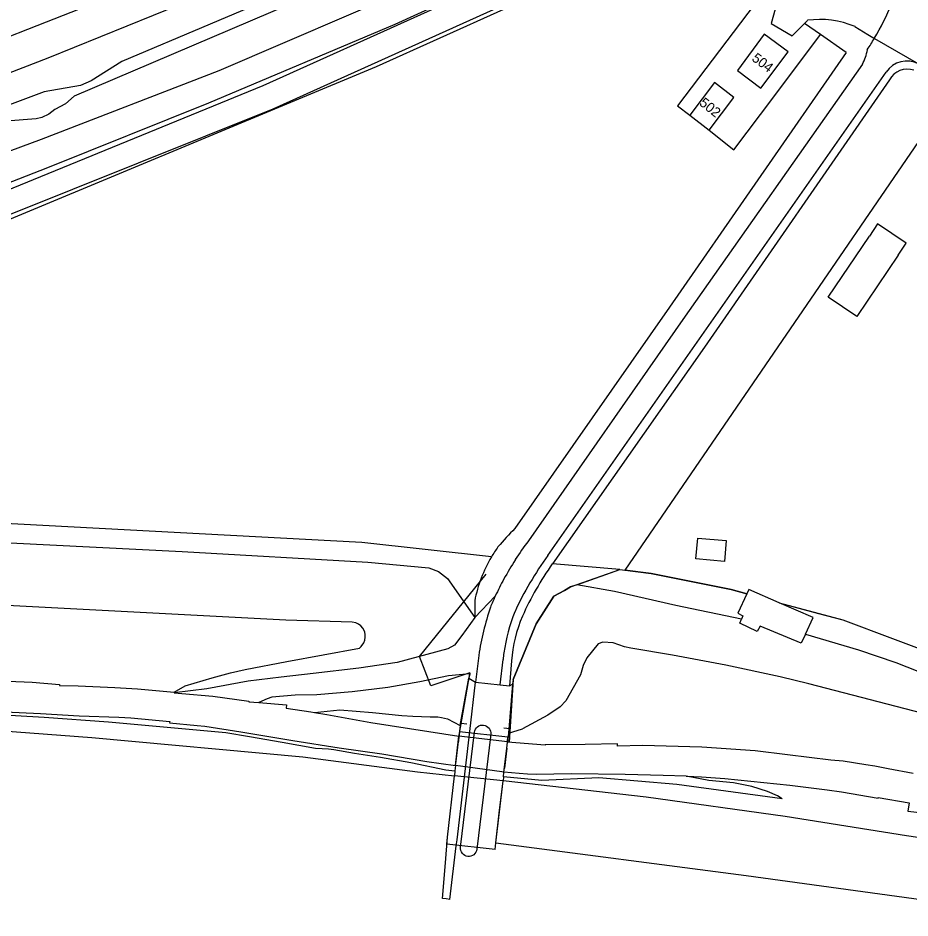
# Model space of a CAD drawing. Extents: x 194485 to 197793, y 468269 to 470822.
# Drawn here: x 195940.6 to 196049.6, y 469112.8 to 469222.9 of the extents above; entities that cross this region are included whole.
import ezdxf

# ---------------------------------------------------------------- set-up
doc = ezdxf.new("R2010")
doc.units = 0
for name, color, linetype in [('BGT begrenzing kruinlijn', 7, 'Continuous'), ('BGT grensvlak begroeid terreindeel', 7, 'Continuous'), ('BGT grensvlak begroeid terreindeel LR', 7, 'Continuous'), ('BGT grensvlak onbegroeid terreindeel', 7, 'Continuous'), ('BGT grensvlak onbegroeid terreindeel plus 1', 7, 'Continuous'), ('BGT grensvlak overbruggingsdeel plus 1', 7, 'Continuous'), ('BGT grensvlak overig bouwwerk uitbreiding populatie', 7, 'Continuous'), ('BGT grensvlak pand op maaiveld', 7, 'Continuous'), ('BGT grensvlak tunneldeel min 1', 7, 'Continuous'), ('BGT grensvlak vegetatieobject', 7, 'Continuous'), ('BGT grensvlak waterdeel', 7, 'Continuous'), ('BGT grensvlak wegdeel', 7, 'Continuous'), ('BGT grensvlak wegdeel plus 1', 7, 'Continuous'), ('BGT lijnelement scheiding hek', 7, 'Continuous'), ('BGT lijnelement spoor trein', 7, 'Continuous'), ('BGT tekst huisnummerreeks', 7, 'Continuous')]:
    doc.layers.add(name, color=color, linetype=linetype)

msp = doc.modelspace()

# ---------------------------------------------------------------- linework, layer by layer
at = {"layer": 'BGT begrenzing kruinlijn'}
for p, q in [((196011.53, 469146.34), (196010.15, 469144.64)), ((196012.1, 469146.57), (196011.53, 469146.34)), ((196013.35, 469146.47), (196012.1, 469146.57)), ((196014.75, 469146), (196013.35, 469146.47)), ((196015.5, 469145.83), (196014.75, 469146)), ((196020.61, 469144.98), (196015.5, 469145.83)), ((196027.15, 469143.77), (196020.61, 469144.98)), ((196009.7, 469143.73), (196009.37, 469142.57)), ((196010.15, 469144.64), (196009.7, 469143.73)), ((196033.79, 469142.31), (196027.15, 469143.77)), ((196009.37, 469142.57), (196007.59, 469139.39)), ((196037.29, 469141.47), (196033.79, 469142.31)), ((196058.8, 469135.89), (196037.29, 469141.47)), ((196007.59, 469139.39), (196006.86, 469138.67)), ((196006.86, 469138.67), (196005.36, 469137.62)), ((196005.36, 469137.62), (196002.27, 469135.98)), ((196000.55, 469135.45), (196002.27, 469135.98))]:
    msp.add_line(p, q, dxfattribs=at)
for points in [[(196011.68, 469240.59), (196004.13, 469237.75), (195988.29, 469230.77), (195947.48, 469213.34), (195946.39, 469212.38), (195945.1, 469211.7), (195944.35, 469211.14), (195943.52, 469210.73), (195942.81, 469210.57), (195939.16, 469210.28), (195897.28, 469195.19), (195879.53, 469189.73), (195853.15, 469181.35), (195844.04, 469178.68), (195834.06, 469175.98)], [(195959.71, 469140.46), (195961.05, 469141.23), (195964.32, 469142.2), (195966.59, 469142.81), (195968.36, 469143.22), (195973.47, 469144.19), (195982.36, 469145.84), (195982.57, 469146.05), (195982.88, 469146.48), (195982.98, 469146.79), (195983.03, 469147.17), (195983.03, 469147.5), (195982.99, 469147.79), (195982.91, 469148.01), (195982.74, 469148.29), (195982.53, 469148.55), (195982.21, 469148.78), (195981.88, 469148.92), (195981.46, 469149), (195973.34, 469149.24), (195926.85, 469151.69), (195915.86, 469151.77)], [(195894.77, 469139.74), (195905.45, 469139.19), (195917.79, 469138.9), (195943.78, 469137.41), (195951.68, 469136.83), (195966.02, 469135.53), (195968.88, 469135.04), (195972.89, 469134.34), (195976.98, 469133.62), (195977.78, 469133.57), (195978.57, 469133.52), (195979.19, 469133.45), (195981.72, 469133.01), (195984.91, 469132.49), (195988.63, 469131.83), (195992.9, 469130.96), (195994.02, 469130.82)], [(195976.85, 469137.97), (195979.96, 469138.28), (195983.94, 469137.98), (195987.53, 469137.61), (195988.86, 469137.5), (195990.98, 469137.44), (195991.91, 469137.43), (195992.36, 469137.37), (195993.1, 469137.17), (195994.66, 469136.39)], [(196034, 469127.39), (196021.12, 469129.16), (196011.62, 469129.99), (196004.65, 469129.64), (195999.94, 469130.08)]]:
    msp.add_lwpolyline(points, dxfattribs=at)
at = {"layer": 'BGT grensvlak begroeid terreindeel'}
for p, q in [((196041.85, 469218.68), (196038.72, 469220.86)), ((196014.18, 469155.45), (196005.92, 469156.14)), ((196008.91, 469153.58), (196014.18, 469155.45)), ((196014.18, 469155.45), (196014.79, 469155.37)), ((195996.43, 469151.62), (195996.45, 469149.56))]:
    msp.add_line(p, q, dxfattribs=at)
for points in [[(195835.93, 469168.56), (195850.59, 469172.63), (195876.12, 469179.94), (195889.94, 469184.48), (195902.05, 469188.58), (195907.49, 469190.51), (195924.09, 469196.72), (195944.24, 469204.6), (195963.93, 469212.5), (195986.7, 469222.13), (196011.58, 469233.49), (196012.58, 469233.54), (196013.02, 469233.37), (196013.69, 469232.61), (196014.11, 469231.67), (196014.15, 469230.9), (196013.89, 469230.29)], [(195856.53, 469168.61), (195883.77, 469178.59), (195931.54, 469194.93), (195984.41, 469216.96), (196000, 469223.96), (196013.89, 469230.29)], [(196041.85, 469218.68), (196020.23, 469187.52), (196001.35, 469160.46)], [(195998.47, 469156.98), (195982.63, 469158.77), (195934.41, 469161.31), (195856.66, 469163.48), (195856.53, 469168.61)], [(195890.63, 469158.09), (195890.8, 469160.9), (195893.82, 469161.05), (195903.99, 469160.77), (195917.76, 469160.03), (195939.63, 469158.73), (195960.68, 469157.64), (195983.36, 469156.35), (195990.82, 469155.67), (195992.01, 469155.2), (195993.11, 469154.34), (195996.45, 469149.56)], [(196008.91, 469153.58), (196008.16, 469153.31), (196007.41, 469152.89), (196006.11, 469152.17), (196003.95, 469148.82), (196001.12, 469141.99), (196001.07, 469141.41)], [(196034, 469127.39), (196033.46, 469127.76), (196032.23, 469128.29), (196030.3, 469128.9), (196028.08, 469129.35), (196025.07, 469129.64), (196022.3, 469130.16)]]:
    msp.add_lwpolyline(points, dxfattribs=at)
for centre, radius, start, end in [((196031.27, 469130.89), 42.07, 135.3274, 139.5072), ((196012.97, 469148.31), 16.9, 144.1568, 149.1153), ((196012.7, 469148.48), 16.57, 149.1356, 169.0648)]:
    msp.add_arc(centre, radius, start, end, dxfattribs=at)
at = {"layer": 'BGT grensvlak begroeid terreindeel LR'}
for points in [[(196013.73, 469236.46), (196009.36, 469235.71), (195989.09, 469226.73), (195965.14, 469216.44), (195943.43, 469208.05), (195918.92, 469198.93), (195901.71, 469192.67), (195890.52, 469188.95), (195875.82, 469184.28), (195841.86, 469174.28), (195834.98, 469172.34)], [(196029.05, 469149.37), (196021.02, 469151.05), (196013.5, 469152.76), (196008.91, 469153.58)], [(196036.85, 469147.53), (196043.36, 469145.61), (196047.9, 469144.08), (196053.3, 469141.96), (196057.4, 469140.11), (196057.99, 469140.01), (196058.36, 469140.14), (196060.06, 469142.05)]]:
    msp.add_lwpolyline(points, dxfattribs=at)
at = {"layer": 'BGT grensvlak onbegroeid terreindeel'}
for p, q in [((196038.72, 469220.86), (196036.74, 469222.23)), ((196032.99, 469213.25), (196038.72, 469220.86)), ((196054.69, 469213.65), (196014.79, 469155.37)), ((195994.66, 469136.39), (195995.72, 469142.17)), ((195959.71, 469140.46), (195959.7, 469140.35)), ((195994.66, 469136.39), (195994.51, 469135.06)), ((195994.51, 469135.06), (195994.43, 469134.41)), ((195994.16, 469132.01), (195994.43, 469134.41)), ((195994.1, 469131.48), (195994.16, 469132.01)), ((195992.88, 469119.59), (195993.1, 469122.71)), ((195992.49, 469115.21), (195992.88, 469119.59)), ((195993.41, 469115.11), (195992.96, 469115.16))]:
    msp.add_line(p, q, dxfattribs=at)
for points in [[(196031.49, 469225.73), (196021.23, 469212.16), (196022.74, 469211.02)], [(196029.69, 469152.48), (196027.77, 469153.02), (196018.02, 469154.97), (196014.79, 469155.37)], [(196033.67, 469151.38), (196038.47, 469150.05), (196041.43, 469149.31), (196053.58, 469144.73), (196060.06, 469142.05)], [(195939.37, 469141.78), (195942.33, 469141.66), (195945.69, 469141.39), (195945.69, 469141.27), (195947.95, 469141.23), (195952.45, 469141.01), (195955.21, 469140.86), (195959.71, 469140.46)], [(195889.55, 469140.07), (195894.51, 469139.87), (195900.64, 469139.68), (195905.53, 469139.58), (195910.28, 469139.37), (195916.6, 469139.16), (195924.84, 469138.78), (195930.12, 469138.47), (195937.25, 469138.12), (195943.33, 469137.84), (195948.09, 469137.55), (195952.92, 469137.38), (195954.4, 469137.3), (195959.15, 469136.86), (195959.12, 469136.7), (195962.51, 469136.39), (195963.44, 469136.31), (195967.82, 469135.6), (195974.19, 469134.54), (195979.88, 469133.66), (195985.06, 469132.91), (195990.56, 469131.99), (195994.1, 469131.48)], [(195970.04, 469139.17), (195973.43, 469138.9), (195973.4, 469138.5), (195976.39, 469138.06), (195976.85, 469137.97)], [(195976.85, 469137.97), (195978.36, 469137.7), (195983.72, 469136.75), (195990.82, 469135.64), (195994.51, 469135.06)], [(196050.05, 469130.52), (196046.97, 469131.08), (196045.33, 469131.42), (196044.26, 469131.58), (196041.46, 469132.01), (196039.96, 469132.15), (196034.65, 469132.78), (196030.7, 469133.28), (196024.18, 469133.73), (196016.94, 469133.94), (196013.9, 469133.86), (196013.9, 469134.14), (196009.92, 469134.07), (196005.05, 469133.99), (196005.05, 469133.95), (196000.43, 469134.34)], [(196022.3, 469130.16), (196019.46, 469130.28), (196014.84, 469130.39), (196008.28, 469130.45), (196003.96, 469130.4), (196002.87, 469130.42), (196001.85, 469130.49), (196000.01, 469130.68)], [(196022.3, 469130.16), (196024.16, 469130.08), (196026.99, 469129.91), (196034.94, 469129.06), (196039.52, 469128.51), (196041.26, 469128.26), (196045.75, 469127.49), (196045.76, 469127.57), (196049.55, 469126.92), (196049.39, 469125.9), (196051.17, 469125.68)]]:
    msp.add_lwpolyline(points, dxfattribs=at)
at = {"layer": 'BGT grensvlak onbegroeid terreindeel plus 1'}
for points in [[(196000.44, 469134.46), (196000.49, 469134.94), (195994.57, 469135.61)], [(196000.01, 469130.68), (195999.73, 469130.71), (195995.6, 469131.26), (195994.1, 469131.48)]]:
    msp.add_lwpolyline(points, dxfattribs=at)
at = {"layer": 'BGT grensvlak overbruggingsdeel plus 1'}
for p, q in [((195994.1, 469131.48), (195994.51, 469135.06)), ((196000.35, 469133.62), (196000.43, 469134.34)), ((196000.01, 469130.68), (196000.35, 469133.62)), ((195994.02, 469130.82), (195993.95, 469130.21)), ((195994.1, 469131.48), (195994.02, 469130.82)), ((195999.94, 469130.08), (196000.01, 469130.68)), ((195993.1, 469122.71), (195993.95, 469130.21)), ((195999.02, 469122.04), (195999.89, 469129.59)), ((195999.94, 469130.08), (195999.89, 469129.59)), ((195993.1, 469122.71), (195993.1, 469122.71)), ((195998.93, 469121.22), (195999.02, 469122.04))]:
    msp.add_line(p, q, dxfattribs=at)
for points in [[(195994.57, 469135.61), (195994.52, 469135.19), (195994.51, 469135.06)], [(196000.44, 469134.46), (196000.5, 469134.94), (195994.57, 469135.61)], [(196000.43, 469134.34), (196000.45, 469134.46), (196000.44, 469134.46)], [(195998.93, 469121.22), (195993.01, 469121.88), (195993.1, 469122.71)]]:
    msp.add_lwpolyline(points, dxfattribs=at)
at = {"layer": 'BGT grensvlak overig bouwwerk uitbreiding populatie'}
for p, q in [((196023.46, 469156.76), (196023.69, 469159.3)), ((196023.69, 469159.3), (196027.19, 469158.98)), ((196027.19, 469158.98), (196026.95, 469156.43)), ((196026.95, 469156.43), (196023.46, 469156.76))]:
    msp.add_line(p, q, dxfattribs=at)
at = {"layer": 'BGT grensvlak pand op maaiveld'}
for p, q in [((196022.74, 469211.02), (196025.09, 469209.17)), ((196048.18, 469193.88), (196043.14, 469186.4))]:
    msp.add_line(p, q, dxfattribs=at)
for points in [[(196028.55, 469216.46), (196031.41, 469214.29), (196034.73, 469218.73), (196031.83, 469220.91), (196028.55, 469216.46)], [(196025.09, 469209.17), (196028.1, 469213.16), (196025.76, 469215.02), (196022.74, 469211.02)], [(196048.18, 469193.88), (196049.17, 469195.34), (196045.68, 469197.7), (196044.69, 469196.23)], [(196043.14, 469186.4), (196039.64, 469188.76), (196044.69, 469196.23)], [(196033.67, 469151.38), (196029.94, 469153), (196029.69, 469152.48)], [(196029.69, 469152.48), (196028.59, 469150.09), (196029.22, 469149.8), (196029.05, 469149.37)], [(196036.85, 469147.53), (196037.8, 469149.58), (196033.67, 469151.38)], [(196036.85, 469147.53), (196036.35, 469146.45), (196031.34, 469148.51), (196030.96, 469147.85), (196028.86, 469148.88), (196029.05, 469149.37)]]:
    msp.add_lwpolyline(points, dxfattribs=at)
at = {"layer": 'BGT grensvlak tunneldeel min 1'}
msp.add_lwpolyline([(195996.4, 469135.55), (195996.45, 469135.74), (195996.52, 469135.92), (195996.64, 469136.08), (195996.78, 469136.22), (195996.94, 469136.33), (195997.13, 469136.4), (195997.32, 469136.43), (195997.52, 469136.43), (195997.71, 469136.38), (195997.89, 469136.3), (195998.05, 469136.19), (195998.18, 469136.05), (195998.29, 469135.89), (195998.36, 469135.7), (195998.39, 469135.51), (195998.39, 469135.31), (195996.7, 469121.24), (195996.65, 469121.05), (195996.57, 469120.87), (195996.46, 469120.71), (195996.32, 469120.57), (195996.15, 469120.47), (195995.97, 469120.4), (195995.78, 469120.36), (195995.58, 469120.36), (195995.39, 469120.41), (195995.21, 469120.49), (195995.05, 469120.6), (195994.92, 469120.74), (195994.81, 469120.91), (195994.74, 469121.09), (195994.71, 469121.28), (195994.71, 469121.48), (195996.4, 469135.55)], dxfattribs=at)
at = {"layer": 'BGT grensvlak vegetatieobject'}
msp.add_line((195992.96, 469115.16), (195992.49, 469115.21), dxfattribs=at)
at = {"layer": 'BGT grensvlak waterdeel'}
for points in [[(196010.71, 469232.72), (195970.53, 469214.58), (195929.37, 469197.77), (195895.42, 469185.55), (195869.04, 469177.09), (195839.77, 469168.98), (195826.39, 469165.62)], [(196011.97, 469229.92), (195971.74, 469211.75), (195930.74, 469195.31), (195896.32, 469183.28), (195870.09, 469174.61), (195840.36, 469166.41), (195826.98, 469163.49)]]:
    msp.add_lwpolyline(points, dxfattribs=at)
at = {"layer": 'BGT grensvlak wegdeel'}
for p, q in [((196036.74, 469222.23), (196037.1, 469222.6)), ((196042.92, 469221.84), (196044.47, 469220.86)), ((196044.47, 469220.86), (196045.29, 469220.39)), ((196045.29, 469220.39), (196050.68, 469217.27)), ((196005.39, 469157.17), (196046.73, 469216.27)), ((195996.45, 469149.56), (195998.95, 469152.2)), ((195996.93, 469144.95), (195996.54, 469141.68)), ((195999.53, 469141.34), (195999.9, 469144.44)), ((196000.94, 469144.28), (196000.67, 469141.21)), ((195995.82, 469142.7), (195995.72, 469142.17)), ((195995.72, 469142.17), (195996.54, 469141.68)), ((195996.54, 469141.68), (195999.53, 469141.34)), ((195999.53, 469141.34), (196000.67, 469141.21)), ((196001.07, 469141.41), (196000.55, 469135.45)), ((196000.67, 469141.21), (196001.07, 469141.41)), ((196000.55, 469135.45), (196000.43, 469134.34)), ((196000.35, 469133.62), (196000.07, 469131.14)), ((196000.01, 469130.68), (196000.07, 469131.14))]:
    msp.add_line(p, q, dxfattribs=at)
for points in [[(196037.09, 469255.65), (196023.81, 469248.66), (196019.52, 469247.02), (196007.14, 469240.9), (196005.89, 469239.7), (196003.16, 469238.42), (195999.24, 469237.41), (195974.88, 469226.72), (195953.31, 469217.56), (195949.53, 469215.22), (195948.23, 469214.64), (195943.81, 469213.84), (195926.15, 469207.25)], [(196033.15, 469223.98), (196032.69, 469222.21), (196035.24, 469220.69), (196036.74, 469222.23)], [(196043.82, 469217.25), (196021.88, 469186.03), (196003, 469158.97)], [(196047.12, 469215.34), (196024.52, 469182.65), (196005.92, 469156.14)], [(195996.45, 469149.56), (195994.87, 469147.36), (195993.94, 469146.21), (195993.13, 469145.73)], [(195993.13, 469145.73), (195986.97, 469144.07), (195982.28, 469143.38), (195976.68, 469142.72), (195972.77, 469142.27), (195968.73, 469141.8), (195963.7, 469140.86), (195959.7, 469140.35)], [(195995.82, 469142.7), (195993.21, 469142.45), (195989.73, 469141.73), (195985.83, 469141.01), (195981.47, 469140.51), (195977.15, 469140.12), (195974.47, 469140.1), (195971.65, 469139.83), (195971.05, 469139.63), (195970.04, 469139.17)], [(195993.41, 469115.11), (195994.18, 469121.67), (195994.27, 469122.38), (195995.74, 469134.94), (195995.83, 469135.66), (195996.54, 469141.68)], [(195959.7, 469140.35), (195960.61, 469140.29), (195964.42, 469139.96), (195968.82, 469139.34), (195968.82, 469139.27), (195970.04, 469139.17)], [(195889.47, 469138.88), (195895.69, 469138.67), (195917.76, 469137.33), (195919, 469137.41), (195920.61, 469137.33), (195924.7, 469136.79), (195949.62, 469134.89), (195975.42, 469132.54), (195989.43, 469130.69), (195993.95, 469130.21)], [(195999.02, 469122.04), (195999.48, 469126.04), (195999.89, 469129.59)], [(196088.32, 469117.26), (196067.43, 469120.21), (196049.2, 469122.88), (196034.4, 469125.24), (196017.38, 469127.61), (195999.89, 469129.59)], [(195999.02, 469122.04), (196029.6, 469118.02), (196057.23, 469114.23), (196080.95, 469110.16), (196100.51, 469106.11), (196139.05, 469098.88), (196174.84, 469090.53), (196207.41, 469082.21), (196234.02, 469074.82), (196264.51, 469065.6), (196275.61, 469062.12), (196277.85, 469061.15), (196295.25, 469055.54), (196322.11, 469046.36), (196335.98, 469041.34), (196360.04, 469032.16), (196376.51, 469025.67), (196401.49, 469015.41), (196430.94, 469002.41)]]:
    msp.add_lwpolyline(points, dxfattribs=at)
for centre, radius, start, end in [((196014.62, 469238.48), 35.6, 329.4621, 337.0942), ((196038.63, 469211.6), 11.11, 67.2704, 97.9105), ((196013.66, 469239.09), 36.74, 326.8676, 329.4053), ((196038.65, 469220.05), 5.88, 331.5447, 349.7326), ((196049.26, 469214.58), 3.04, 62.1732, 146.2269), ((196049.32, 469214.11), 2.51, 71.3631, 150.8553), ((196033.62, 469136.02), 38.27, 143.1568, 147.3757), ((196036.94, 469134.01), 39.14, 143.7317, 155.4858), ((196033.47, 469136.16), 38.06, 147.424, 151.5517), ((196036.7, 469134.34), 37.72, 144.6889, 155.8966), ((196034.15, 469135.82), 38.83, 151.5861, 155.0431), ((196034.66, 469135.66), 39.36, 155.1507, 157.3222), ((196031.27, 469139.82), 34.72, 161.4994, 171.5025), ((196020.67, 469142.42), 20.86, 157.9437, 172.1218), ((196018.42, 469142.92), 17.54, 157.0862, 175.5428), ((196019.13, 469142.59), 19.32, 171.9979, 174.495)]:
    msp.add_arc(centre, radius, start, end, dxfattribs=at)
at = {"layer": 'BGT grensvlak wegdeel plus 1'}
msp.add_line((195999.89, 469129.59), (195993.95, 469130.21), dxfattribs=at)
at = {"layer": 'BGT lijnelement scheiding hek'}
for p, q in [((196028.12, 469206.78), (196032.99, 469213.25)), ((196025.09, 469209.17), (196028.12, 469206.78)), ((195995.83, 469142.81), (195995.82, 469142.7)), ((195994.77, 469136.66), (195995.46, 469136.59)), ((195999.98, 469136.08), (196000.73, 469135.99)), ((196000.44, 469134.37), (195994.51, 469135.06))]:
    msp.add_line(p, q, dxfattribs=at)
for points in [[(195995.83, 469142.81), (195991.05, 469141.21), (195989.67, 469144.83), (195997.84, 469154.88)], [(196007.41, 469152.89), (196008.16, 469153.31), (196014.18, 469155.45), (196018.02, 469154.97), (196027.77, 469153.02), (196029.69, 469152.48)], [(196001.12, 469141.99), (196003.95, 469148.82), (196006.11, 469152.17), (196007.41, 469152.89)], [(196033.67, 469151.38), (196041.43, 469149.31), (196053.58, 469144.73), (196060.06, 469142.05)], [(195994.51, 469135.06), (195994.52, 469135.19), (195995.82, 469142.7)], [(196001.12, 469141.99), (196000.63, 469134.35), (196000.44, 469134.37)]]:
    msp.add_lwpolyline(points, dxfattribs=at)
at = {"layer": 'BGT lijnelement spoor trein'}
for points in [[(195831.59, 469185.8), (195837.36, 469187.3), (195853.27, 469191.7), (195861.18, 469193.98), (195878.34, 469199.18), (195887.16, 469201.99), (195895.23, 469204.63), (195914.21, 469211.17), (195924.34, 469214.84), (195933.37, 469218.21), (195942.93, 469221.95), (195953.55, 469226.16), (195971.75, 469233.76), (195989.64, 469241.67), (195998.23, 469245.62), (196007.36, 469249.9), (196026.34, 469259.12), (196034.36, 469263.12)], [(195832.59, 469181.84), (195838.96, 469183.48), (195856.59, 469188.36), (195868, 469191.69), (195885.85, 469197.22), (195898.36, 469201.32), (195917.66, 469208.03), (195935.09, 469214.46), (195944.28, 469218.03), (195963.6, 469225.9), (195973.98, 469230.3), (195992.73, 469238.64), (196012.7, 469247.97), (196022.89, 469252.93), (196036.13, 469259.51)]]:
    msp.add_lwpolyline(points, dxfattribs=at)

# ---------------------------------------------------------------- texts
at = {"layer": 'BGT tekst huisnummerreeks'}
for s, rotation, p in [('504', 323, (196030.21, 469217.76)), ('502', 321.5, (196023.8, 469212.32))]:
    msp.add_text(s, height=1.2, rotation=rotation, dxfattribs=at).set_placement(p)

doc.saveas('drawing.dxf')
